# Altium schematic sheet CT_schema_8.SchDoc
size 287 x 160 mm
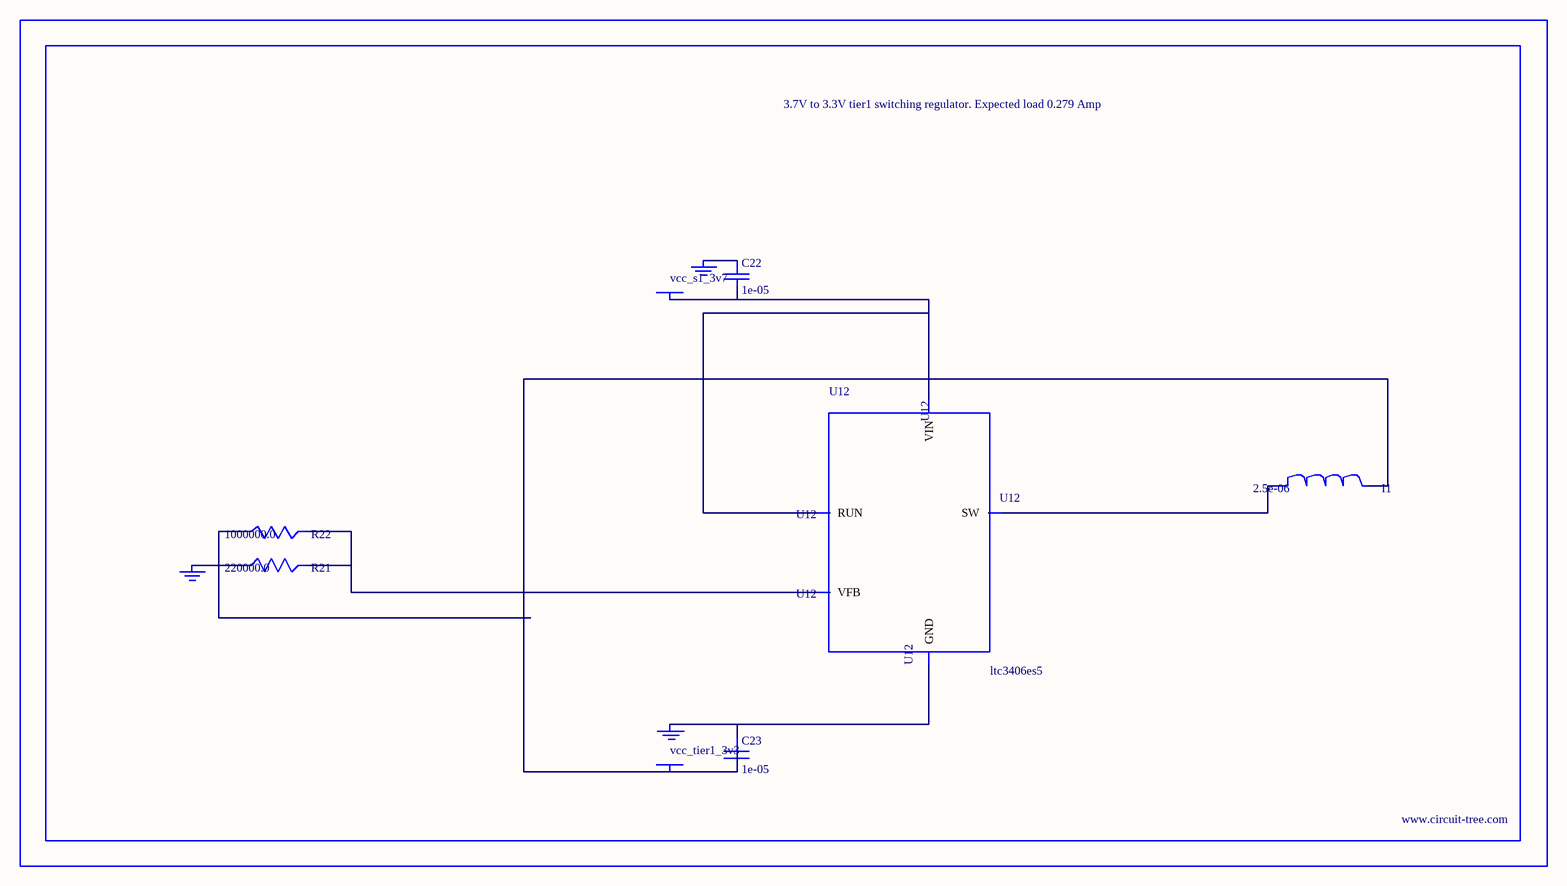
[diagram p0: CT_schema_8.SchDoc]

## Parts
BORDER7  (no value)
C22  1e-05  [C0805]
C23  1e-05  [C0805]
GND_INSTANCE_7_0  (no value)
GND_INSTANCE_7_1  (no value)
GND_INSTANCE_7_2  (no value)
I1  2.5e-06  [DR1040]
POWER_INSTANCE_7_0  vcc_tier1_3v3
POWER_INSTANCE_7_1  vcc_s1_3v7
R21  220000.0  [R0603]
R22  1000000.0  [R0603]
U12  ltc3406es5  [TSOT-23-5]

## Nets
NetC22_1: C22.1 GND_INSTANCE_7_1.0(GND)
NetC22_2: C22.2 POWER_INSTANCE_7_1.0(PWR) U12.1(RUN) U12.4(VIN)
NetC23_1: C23.1 GND_INSTANCE_7_0.0(GND) U12.2(GND)
NetC23_2: C23.2 I1.2 POWER_INSTANCE_7_0.0(PWR) R22.1
NetGND_INSTANCE_7_2_0: GND_INSTANCE_7_2.0(GND) R21.1
NetI1_1: I1.1 U12.3(SW)
NetR21_2: R21.2 R22.2 U12.5(VFB)

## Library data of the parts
BORDER7 = BORDER_PAGE7
C22 C23 = C0805C106K8RACTU
GND_INSTANCE_7_0-GND_INSTANCE_7_2 = GND
I1 = DR1040-2R5-R
POWER_INSTANCE_7_0 POWER_INSTANCE_7_1 = PWR
R21 = RC0603JR-07220KL
R22 = RC0603JR-071ML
